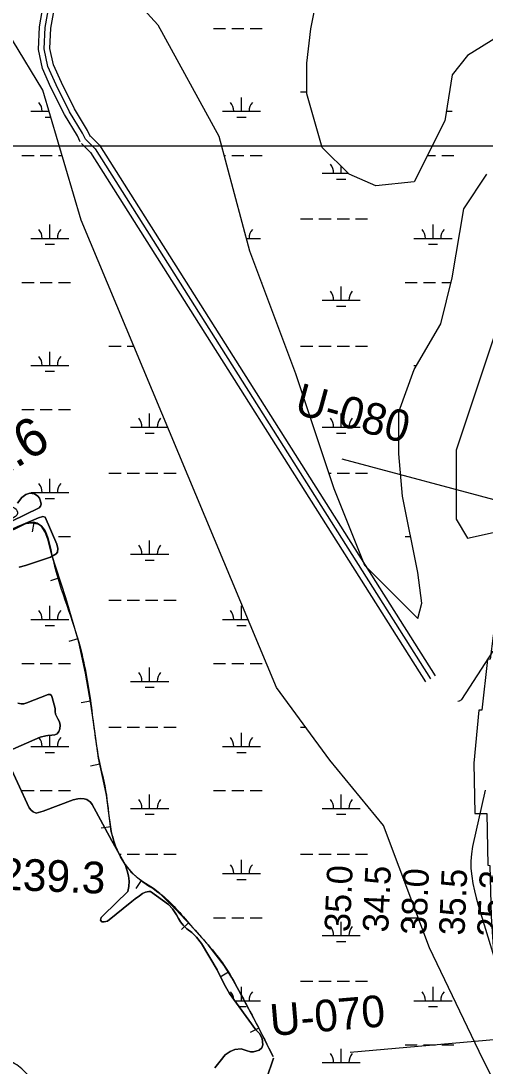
# Model space of a CAD drawing. Extents: x 3281947 to 3319794, y 715894 to 741249.
# Drawn here: x 3293405 to 3294621, y 730987 to 733724 of the extents above; entities that cross this region are included whole.
import ezdxf

# ---------------------------------------------------------------- set-up
doc = ezdxf.new("R2010")
doc.units = 0
for name, color, linetype in [('V-BORW-LINE', 7, 'Continuous'), ('V-GRID-MAJR', 7, 'Continuous'), ('V-RIVR-RANG', 7, 'Continuous'), ('V-RIVR-RANG-IDEN', 7, 'Continuous'), ('V-ROAD-CNTR', 7, 'Continuous'), ('V-RRAP-RVMT', 7, 'Continuous'), ('V-SITE-VEGE', 7, 'Continuous'), ('V-SURV-IDEN', 7, 'Continuous'), ('V-TOPO-MINR', 7, 'Continuous'), ('V-WETL-SWMP', 7, 'Continuous')]:
    doc.layers.add(name, color=color, linetype=linetype)

msp = doc.modelspace()

# ---------------------------------------------------------------- linework, layer by layer
at = {"layer": 'V-BORW-LINE'}
for p, q in [((3293438.9, 732410.6), (3293434.1, 732386.1)), ((3293505.8, 732265.2), (3293482, 732257.5)), ((3293554, 732105.8), (3293530, 732098.8)), ((3293586.8, 731942.5), (3293562.2, 731938.2)), ((3293611.6, 731777.8), (3293587.1, 731772.8)), ((3293640, 731613.7), (3293615.2, 731610.4)), ((3293720.1, 731472.8), (3293705.8, 731452.3)), ((3293843.5, 731362.2), (3293825.3, 731345.1)), ((3293948.3, 731233), (3293927, 731219.7)), ((3294027.8, 731086.6), (3294005.5, 731075.3))]:
    msp.add_line(p, q, dxfattribs=at)
for points in [[(3294065.4, 731012.3), (3294021.6, 731098.9), (3293976, 731184.6), (3293957.6, 731218), (3293937.4, 731250.3), (3293895.2, 731304.6), (3293849.4, 731356), (3293809.7, 731398.2), (3293768.8, 731439), (3293752, 731452.5), (3293724.5, 731469.8), (3293711, 731479.2), (3293698.6, 731490.3), (3293678.2, 731515.3), (3293665.5, 731535.4), (3293650.9, 731567.6), (3293641.6, 731601.6), (3293635.2, 731649.3), (3293628.6, 731696.8), (3293618.2, 731745.2), (3293608.4, 731793.7), (3293598.1, 731864.4), (3293588.1, 731935.2), (3293573.9, 732016.3), (3293556.5, 732096.9), (3293522.7, 732213.3), (3293485.1, 732328.5), (3293475.3, 732366.4), (3293468.6, 732384.7), (3293457.9, 732401.3), (3293447.7, 732408.8), (3293437.4, 732410.9), (3293417.2, 732406.7), (3293352.9, 732375.1)], [(3294066.6, 731007.9), (3294048.3, 730953.6), (3294015.3, 730962.9), (3293968.2, 730832.8), (3293984.4, 730712.4), (3294025, 730625.2), (3294125.7, 730665.2), (3294411.3, 730593.9), (3294443.6, 730454.8), (3294455, 730377), (3294542.3, 730379.8), (3294572, 730312), (3294499.3, 730155.1), (3294304.7, 730084.1), (3294182.8, 729985.9), (3294081.7, 729899.7), (3294039.9, 729833.7), (3293988.3, 729835.4), (3293949.1, 729896), (3293892.4, 730001.9), (3293812.2, 730136.7), (3293762.4, 730233), (3293692.2, 730362.3), (3293538.9, 730574.2)], [(3293538.9, 730574.2), (3293692.2, 730362.3), (3293762.4, 730233), (3293812.2, 730136.7), (3293892.4, 730001.9), (3293949.1, 729896), (3293988.3, 729835.4), (3294039.9, 729833.7), (3294084.7, 729890.8), (3294221.5, 730018.7), (3294337.4, 730090), (3294499.3, 730155.1), (3294572, 730312), (3294542.3, 730379.8), (3294455, 730377), (3294443.6, 730454.8), (3294411.3, 730593.9), (3294125.7, 730665.2), (3294025, 730625.2), (3293984.4, 730712.4), (3293968.2, 730832.8), (3294015.3, 730962.9), (3294048.3, 730953.6), (3294066.6, 731007.9)]]:
    msp.add_lwpolyline(points, dxfattribs=at)
msp.add_spline([(3293535.9, 730584.4), (3293535.4, 730585.3), (3293497, 730657.8), (3293473.2, 730709), (3293458.5, 730751), (3293474.3, 730774.9), (3293498.1, 730803.8), (3293503.4, 730822.7), (3293477.8, 730865.6), (3293442, 730902.7), (3293433.9, 730945), (3293411.4, 730975.9), (3293373.6, 730999.6), (3293329.4, 731009.5), (3293303.1, 731048.1), (3293262.2, 731107.9), (3293205.3, 731214.8), (3293152.6, 731305), (3293107.1, 731394.1), (3293067.5, 731500.7), (3293026.1, 731639), (3292993.6, 731735.4), (3292952.7, 731872.8), (3292925.4, 731981.1), (3292877.6, 732144.9), (3292823.1, 732324.3), (3292751.1, 732547.8), (3292686.3, 732753.5), (3292626.9, 732959.9), (3292578, 733149.6), (3292517.3, 733327.2), (3292468.2, 733513.4), (3292419.2, 733671.8), (3292416, 733774.3), (3292443.1, 733955.9), (3292470.5, 734116.1), (3292505.3, 734342.4), (3292539, 734502.7), (3292585.4, 734750.4), (3292605.6, 734909.3), (3292653.5, 735109.1), (3292667, 735197.9), (3292695.9, 735272.4), (3292816.4, 735423.9), (3292992.8, 735589.4), (3293118.5, 735717.8), (3293151.4, 735720.6), (3293212.8, 735688.5), (3293267.6, 735628.9), (3293299.6, 735578.7), (3293301.8, 735551.8), (3293258, 735404.8), (3293178.9, 735247.8), (3293118.6, 735154.6), (3293020.3, 735075.8), (3292963, 735023.3), (3292899.5, 734947.4), (3292877.5, 734825.5), (3292893.6, 734715.3), (3292909.1, 734596.9), (3292894.2, 734486.7), (3292877, 734359.2), (3292869.2, 734210.8), (3292882, 734024.1), (3292899.4, 733885.4), (3292922.7, 733752.5), (3292923.7, 733661.1), (3292932, 733561), (3292981.6, 733412.2), (3293062.5, 733212.5), (3293111.5, 733047.6), (3293198.7, 732785.6), (3293276, 732606.5), (3293315.6, 732497), (3293336.7, 732448.1), (3293389.1, 732447.8), (3293396.1, 732434.3), (3293380.9, 732420.2), (3293299, 732384.1), (3293266.7, 732364.9), (3293242, 732348.4), (3293249.1, 732332.4), (3293352.9, 732375.1), (3293457.9, 732401.3), (3293485.1, 732328.5), (3293556.5, 732096.9), (3293588.1, 731935.2), (3293608.4, 731793.7), (3293628.6, 731696.8), (3293641.6, 731601.6), (3293698.6, 731490.3), (3293768.8, 731439), (3293849.4, 731356), (3293937.4, 731250.3), (3293976, 731184.6), (3294065.4, 731012.3)], degree=3, dxfattribs=at)
at = {"layer": 'V-GRID-MAJR'}
msp.add_spline([(3286081.5, 733394.4), (3291329.7, 733395.6), (3296577.9, 733397.5), (3301826.1, 733400.1), (3307074.3, 733403.6), (3312322.5, 733407.8), (3317570.7, 733412.7)], degree=3, dxfattribs=at)
at = {"layer": 'V-RIVR-RANG'}
for p, q in [((3294245.3, 732577.4), (3295520.5, 732236.1)), ((3294266.9, 731023.3), (3295442.3, 731126.6))]:
    msp.add_line(p, q, dxfattribs=at)
at = {"layer": 'V-ROAD-CNTR'}
for points in [[(3293560.3, 733407.4), (3293552.9, 733422.8), (3293518.9, 733478.9), (3293483.5, 733549.6), (3293461.3, 733599.4), (3293450.6, 733649.1), (3293453.2, 733708.2), (3293463.8, 733768.2)], [(3293573.8, 733414), (3293566.1, 733429.9), (3293532.1, 733486.1), (3293497.1, 733556), (3293475.6, 733604.1), (3293465.6, 733650.4), (3293468.1, 733706.6), (3293478.5, 733765.3)], [(3293587.3, 733420.5), (3293579.3, 733437.1), (3293545.2, 733493.4), (3293510.7, 733562.5), (3293490, 733608.8), (3293480.7, 733651.7), (3293483, 733704.9), (3293493.3, 733762.5)], [(3293573.8, 733414), (3293599.3, 733389), (3294477.3, 732001.2)], [(3293584.3, 733424.7), (3293611, 733398.5), (3294489.9, 732009.2)], [(3293563.3, 733403.2), (3293587.5, 733379.5), (3294464.6, 731993.1)]]:
    msp.add_lwpolyline(points, dxfattribs=at)
at = {"layer": 'V-RRAP-RVMT'}
msp.add_lwpolyline([(3294917, 732419.7), (3294695.4, 732452.1), (3294671.8, 732315.8), (3294667.4, 732316.1), (3294647.2, 732175.3), (3294649.4, 732174.7), (3294634, 732052.3), (3294626.5, 732052.1), (3294612.3, 731919.3), (3294603.8, 731919.4), (3294591, 731780.6), (3294593.8, 731648.3), (3294624.8, 731648.7), (3294627.6, 731512.8), (3294632.8, 731512.7), (3294636.8, 731379.2), (3294644.9, 731245.9), (3294672.3, 731248.1)], dxfattribs=at)
at = {"layer": 'V-SITE-VEGE'}
for points in [[(3293396.1, 732460.9), (3293406.8, 732475.7), (3293418, 732483.9), (3293428.5, 732487.3), (3293440, 732485.2), (3293449.1, 732479.6), (3293453.1, 732473.8), (3293455.9, 732465.9), (3293457.6, 732458.4), (3293456, 732453), (3293453, 732448.6), (3293379.3, 732412.9)], [(3293308.2, 732362.6), (3293450.5, 732422.4), (3293462, 732425.7), (3293468.3, 732424.5), (3293468.5, 732424.8), (3293499.2, 732353.6), (3293501.2, 732342.2), (3293500.3, 732332.8), (3293496.8, 732328.1), (3293482.1, 732319.6), (3293417, 732297.4), (3293400.2, 732293.5)], [(3293397.1, 731937.7), (3293405.1, 731935.6), (3293412.8, 731935.7), (3293420.3, 731938), (3293476.5, 731959.8), (3293481.4, 731960.1), (3293484.5, 731957.7), (3293486.4, 731952.4), (3293494.7, 731923), (3293494.7, 731915.2), (3293495.2, 731908.2), (3293497.6, 731902.9), (3293501.6, 731896.6), (3293506.1, 731888.4), (3293507.7, 731879.5), (3293506.6, 731869.9), (3293504.3, 731862.9), (3293499.4, 731857.5), (3293493.8, 731854.7), (3293485.9, 731853.5), (3293475.6, 731852.3), (3293469.8, 731852), (3293455.3, 731848.2), (3293369.9, 731810.9)], [(3293365.3, 731796.1), (3293426.7, 731663.6), (3293431.6, 731656.8), (3293436.8, 731652.7), (3293445.2, 731649.2), (3293463.4, 731654.7), (3293541.6, 731684.2), (3293553.5, 731687.1), (3293561.5, 731687.8), (3293570.8, 731687.2)], [(3293570.8, 731687.2), (3293577.8, 731684.9), (3293586.8, 731678.4), (3293591.5, 731672.1), (3293601.8, 731653.2), (3293642.9, 731577.2), (3293678.2, 731515.1), (3293683.4, 731498.1), (3293686.3, 731485.3), (3293688.2, 731471.2), (3293687.8, 731457.4), (3293684.9, 731444.1), (3293621.3, 731382.6), (3293615.3, 731376.4), (3293613, 731369), (3293617, 731364.8), (3293623.3, 731364.6), (3293631.7, 731366.9), (3293695.5, 731417.7), (3293704.1, 731424.6), (3293715.1, 731433), (3293723.7, 731439.1), (3293731.4, 731442.9), (3293740, 731444.6), (3293744, 731444.1), (3293791.2, 731410), (3293801.5, 731398.8), (3293812.3, 731383.4), (3293817.5, 731373.4), (3293822.5, 731365), (3293830, 731355.9), (3293839.8, 731346.6), (3293852.5, 731336.6), (3293865, 731325), (3293877.7, 731308.2), (3293918.4, 731238.7), (3293936.8, 731201.9), (3293951.4, 731177.2), (3294020.4, 731082.3), (3294029.8, 731072.3), (3294037.1, 731059.3), (3294038.3, 731043.1), (3294036, 731034.5), (3294028.8, 731028.4), (3294014.1, 731024.6), (3294006.4, 731024.3), (3293994.7, 731027.7), (3293982, 731032.4), (3293965.2, 731030.9), (3293953.3, 731025.7), (3293939.8, 731016.3), (3293926.3, 731000.3), (3293912.4, 730982.7)]]:
    msp.add_lwpolyline(points, dxfattribs=at)
at = {"layer": 'V-TOPO-MINR'}
for points in [[(3294549.5, 731942.9), (3294553.9, 731943.4), (3294559.9, 731946.6), (3294641.3, 732073.6)], [(3294620.8, 731709.7), (3294588, 731561.8), (3294584.9, 731542.7), (3294583.2, 731523.4), (3294583.6, 731504.1), (3294585.5, 731484.8), (3294588.8, 731465.5), (3294592.8, 731446.4), (3294597.5, 731427.4), (3294602.8, 731408.5), (3294738.5, 730962.5)]]:
    msp.add_lwpolyline(points, dxfattribs=at)
at = {"layer": 'V-WETL-SWMP'}
for p, q in [((3293909, 733704.3), (3293941, 733704.3)), ((3293957, 733704.3), (3293989, 733704.3)), ((3294005, 733704.3), (3294037, 733704.3)), ((3293982.4, 733487.1), (3293982.4, 733523.1)), ((3294137, 733537.8), (3294153.9, 733537.8)), ((3293430.5, 733487.1), (3293478.9, 733487.1)), ((3293468.5, 733471.6), (3293483.4, 733471.6)), ((3293932.4, 733487.1), (3294032.4, 733487.1)), ((3293970.4, 733471.6), (3293994.4, 733471.6)), ((3294518.8, 733487.1), (3294534.3, 733487.1)), ((3293407.1, 733371.6), (3293439.1, 733371.6)), ((3293455.1, 733371.6), (3293487.1, 733371.6)), ((3293503.1, 733371.6), (3293512.8, 733371.6)), ((3293937, 733371.6), (3293941, 733371.6)), ((3293957, 733371.6), (3293989, 733371.6)), ((3294005, 733371.6), (3294037, 733371.6)), ((3294469.3, 733371.6), (3294490.9, 733371.6)), ((3294506.9, 733371.6), (3294538.9, 733371.6)), ((3294193.8, 733325.2), (3294261, 733325.2)), ((3294243.8, 733325.2), (3294243.8, 733342.4)), ((3294231.8, 733309.8), (3294255.8, 733309.8)), ((3293480.5, 733154.4), (3293480.5, 733190.4)), ((3294137, 733205.1), (3294169, 733205.1)), ((3294185, 733205.1), (3294217, 733205.1)), ((3294233, 733205.1), (3294265, 733205.1)), ((3294281, 733205.1), (3294313, 733205.1)), ((3294484.3, 733154.4), (3294484.3, 733190.4)), ((3293430.5, 733154.4), (3293530.5, 733154.4)), ((3293468.5, 733139), (3293492.5, 733139)), ((3293994.9, 733154.4), (3294032.4, 733154.4)), ((3294434.3, 733154.4), (3294534.3, 733154.4)), ((3294472.3, 733139), (3294496.3, 733139)), ((3293407.1, 733039), (3293439.1, 733039)), ((3293455.1, 733039), (3293487.1, 733039)), ((3293503.1, 733039), (3293535.1, 733039)), ((3294034.6, 733039), (3294037, 733039)), ((3294243.8, 732992.5), (3294243.8, 733028.5)), ((3294410.9, 733039), (3294442.9, 733039)), ((3294458.9, 733039), (3294490.9, 733039)), ((3294506.9, 733039), (3294531.7, 733039)), ((3294193.8, 732992.5), (3294293.8, 732992.5)), ((3294231.8, 732977.1), (3294255.8, 732977.1)), ((3293635.1, 732872.5), (3293667.1, 732872.5)), ((3293683.1, 732872.5), (3293700.3, 732872.5)), ((3294137, 732872.5), (3294169, 732872.5)), ((3294185, 732872.5), (3294217, 732872.5)), ((3294233, 732872.5), (3294265, 732872.5)), ((3294281, 732872.5), (3294313, 732872.5)), ((3293480.5, 732821.7), (3293480.5, 732857.7)), ((3293430.5, 732821.7), (3293530.5, 732821.7)), ((3293468.5, 732806.3), (3293492.5, 732806.3)), ((3294434.3, 732821.7), (3294441, 732821.7)), ((3293407.1, 732706.3), (3293439.1, 732706.3)), ((3293455.1, 732706.3), (3293487.1, 732706.3)), ((3293503.1, 732706.3), (3293535.1, 732706.3)), ((3293741.9, 732659.9), (3293741.9, 732695.9)), ((3294243.8, 732659.9), (3294243.8, 732695.9)), ((3293691.9, 732659.9), (3293789.1, 732659.9)), ((3293729.9, 732644.4), (3293753.9, 732644.4)), ((3294193.8, 732659.9), (3294293.8, 732659.9)), ((3294231.8, 732644.4), (3294255.8, 732644.4)), ((3293635.1, 732539.8), (3293667.1, 732539.8)), ((3293683.1, 732539.8), (3293715.1, 732539.8)), ((3293731.1, 732539.8), (3293763.1, 732539.8)), ((3293779.1, 732539.8), (3293811.1, 732539.8)), ((3294210.7, 732539.8), (3294217, 732539.8)), ((3294233, 732539.8), (3294265, 732539.8)), ((3294281, 732539.8), (3294313, 732539.8)), ((3293480.5, 732489), (3293480.5, 732525)), ((3293430.5, 732489), (3293530.5, 732489)), ((3293468.5, 732473.6), (3293492.5, 732473.6)), ((3293503.1, 732373.6), (3293535.1, 732373.6)), ((3294410.9, 732373.6), (3294425.7, 732373.6)), ((3293741.9, 732327.2), (3293741.9, 732363.2)), ((3293691.9, 732327.2), (3293791.9, 732327.2)), ((3294293, 732327.2), (3294293.8, 732327.2)), ((3293729.9, 732311.7), (3293753.9, 732311.7)), ((3293635.1, 732207.1), (3293667.1, 732207.1)), ((3293683.1, 732207.1), (3293715.1, 732207.1)), ((3293731.1, 732207.1), (3293763.1, 732207.1)), ((3293779.1, 732207.1), (3293811.1, 732207.1)), ((3293480.5, 732156.4), (3293480.5, 732192.4)), ((3293982.4, 732156.4), (3293982.4, 732192.4)), ((3293430.5, 732156.4), (3293530.5, 732156.4)), ((3293932.4, 732156.4), (3293999.4, 732156.4)), ((3293468.5, 732140.9), (3293492.5, 732140.9)), ((3293970.4, 732140.9), (3293994.4, 732140.9)), ((3293407.1, 732040.9), (3293439.1, 732040.9)), ((3293455.1, 732040.9), (3293487.1, 732040.9)), ((3293503.1, 732040.9), (3293535.1, 732040.9)), ((3293909, 732040.9), (3293941, 732040.9)), ((3293957, 732040.9), (3293989, 732040.9)), ((3294005, 732040.9), (3294037, 732040.9)), ((3293741.9, 731994.5), (3293741.9, 732030.5)), ((3293691.9, 731994.5), (3293791.9, 731994.5)), ((3293729.9, 731979.1), (3293753.9, 731979.1)), ((3293635.1, 731874.4), (3293667.1, 731874.4)), ((3293683.1, 731874.4), (3293715.1, 731874.4)), ((3293731.1, 731874.4), (3293763.1, 731874.4)), ((3293779.1, 731874.4), (3293811.1, 731874.4)), ((3294137, 731874.4), (3294150.2, 731874.4)), ((3293480.5, 731823.7), (3293480.5, 731852.8)), ((3293982.4, 731823.7), (3293982.4, 731859.7)), ((3293430.5, 731823.7), (3293530.5, 731823.7)), ((3293932.4, 731823.7), (3294032.4, 731823.7)), ((3293468.5, 731808.3), (3293492.5, 731808.3)), ((3293970.4, 731808.3), (3293994.4, 731808.3)), ((3293407.1, 731708.3), (3293439.1, 731708.3)), ((3293455.1, 731708.3), (3293487.1, 731708.3)), ((3293503.1, 731708.3), (3293535.1, 731708.3)), ((3293741.9, 731661.8), (3293741.9, 731697.8)), ((3293909, 731708.3), (3293941, 731708.3)), ((3293957, 731708.3), (3293989, 731708.3)), ((3294005, 731708.3), (3294037, 731708.3)), ((3294243.8, 731661.8), (3294243.8, 731697.8)), ((3293691.9, 731661.8), (3293791.9, 731661.8)), ((3294193.8, 731661.8), (3294293.8, 731661.8)), ((3293729.9, 731646.4), (3293753.9, 731646.4)), ((3294231.8, 731646.4), (3294255.8, 731646.4)), ((3293663.1, 731541.8), (3293667.1, 731541.8)), ((3293683.1, 731541.8), (3293715.1, 731541.8)), ((3293731.1, 731541.8), (3293763.1, 731541.8)), ((3293779.1, 731541.8), (3293811.1, 731541.8)), ((3293982.4, 731491), (3293982.4, 731527)), ((3294137, 731541.8), (3294169, 731541.8)), ((3294185, 731541.8), (3294217, 731541.8)), ((3294233, 731541.8), (3294265, 731541.8)), ((3294281, 731541.8), (3294313, 731541.8)), ((3293932.4, 731491), (3294032.4, 731491)), ((3293970.4, 731475.6), (3293994.4, 731475.6)), ((3293909, 731375.6), (3293941, 731375.6)), ((3293957, 731375.6), (3293989, 731375.6)), ((3294005, 731375.6), (3294037, 731375.6)), ((3294243.8, 731329.2), (3294243.8, 731365.2)), ((3294410.9, 731375.6), (3294442.9, 731375.6)), ((3294193.8, 731329.2), (3294293.8, 731329.2)), ((3294231.8, 731313.7), (3294255.8, 731313.7)), ((3293982.4, 731158.3), (3293982.4, 731194.3)), ((3294137, 731209.1), (3294169, 731209.1)), ((3294185, 731209.1), (3294217, 731209.1)), ((3294233, 731209.1), (3294265, 731209.1)), ((3294281, 731209.1), (3294313, 731209.1)), ((3294484.3, 731158.3), (3294484.3, 731194.3)), ((3293965.1, 731158.3), (3294032.4, 731158.3)), ((3293976.4, 731142.9), (3293994.4, 731142.9)), ((3294434.3, 731158.3), (3294534.3, 731158.3)), ((3294472.3, 731142.9), (3294496.3, 731142.9)), ((3294243.8, 730996.5), (3294243.8, 731032.5)), ((3294410.9, 731042.9), (3294442.9, 731042.9)), ((3294458.9, 731042.9), (3294490.9, 731042.9)), ((3294506.9, 731042.9), (3294538.9, 731042.9)), ((3294193.8, 730996.5), (3294293.8, 730996.5))]:
    msp.add_line(p, q, dxfattribs=at)
for points in [[(3294819.9, 730595.5), (3294614.9, 731005.5), (3294474.6, 731296.3), (3294354.4, 731617.2), (3294214.1, 731787.7), (3294073.8, 731978.2), (3293562.7, 733201.7), (3293462.5, 733542.7), (3293382.4, 733673.1), (3293352.3, 733793.4), (3293412.4, 733883.7), (3293492.6, 733913.7), (3293612.8, 733883.7), (3293673, 733813.5), (3293763.1, 733713.2)], [(3294655, 733683.1), (3294574.8, 733632.9), (3294534.7, 733582.8), (3294514.7, 733462.5), (3294434.5, 733302), (3294334.3, 733292), (3294264.2, 733322.1), (3294194, 733392.3), (3294154, 733532.7), (3294154, 733612.9), (3294164, 733703.1), (3294184, 733803.4)], [(3293763.1, 733713.2), (3293923.5, 733422.3), (3294003.6, 733121.5), (3294123.9, 732800.6), (3294224.1, 732499.7), (3294304.3, 732299.1), (3294444.6, 732158.7), (3294454.6, 732198.9), (3294444.6, 732279.1), (3294404.5, 732479.7), (3294394.4, 732590), (3294394.4, 732700.3), (3294434.5, 732810.6), (3294504.7, 732930.9), (3294534.7, 733051.3), (3294564.8, 733231.8), (3294624.9, 733322.1)], [(3294645, 732900.9), (3294544.8, 732600), (3294544.8, 732419.5), (3294574.8, 732369.3), (3294665, 732389.4)], [(3293379.3, 732412.9), (3293453, 732448.6), (3293456, 732453), (3293457.6, 732458.4), (3293455.9, 732465.9), (3293453.1, 732473.8), (3293449.1, 732479.6), (3293440, 732485.2), (3293428.5, 732487.3), (3293418, 732483.9), (3293406.8, 732475.7), (3293396.1, 732460.9)], [(3293400.2, 732293.5), (3293417, 732297.4), (3293482.1, 732319.6), (3293496.8, 732328.1), (3293500.3, 732332.8), (3293501.2, 732342.2), (3293499.2, 732353.6), (3293468.5, 732424.8), (3293468.3, 732424.5), (3293462, 732425.7), (3293450.5, 732422.4), (3293308.2, 732362.6)], [(3293369.9, 731810.9), (3293455.3, 731848.2), (3293469.8, 731852), (3293475.6, 731852.3), (3293485.9, 731853.5), (3293493.8, 731854.7), (3293499.4, 731857.5), (3293504.3, 731862.9), (3293506.6, 731869.9), (3293507.7, 731879.5), (3293506.1, 731888.4), (3293501.6, 731896.6), (3293497.6, 731902.9), (3293495.2, 731908.2), (3293494.7, 731915.2), (3293494.7, 731923), (3293486.4, 731952.4), (3293484.5, 731957.7), (3293481.4, 731960.1), (3293476.5, 731959.8), (3293420.3, 731938), (3293412.8, 731935.7), (3293405.1, 731935.6)], [(3293405.1, 731935.6), (3293397.1, 731937.7)], [(3293912.4, 730982.7), (3293926.3, 731000.3), (3293939.8, 731016.3), (3293953.3, 731025.7), (3293965.2, 731030.9), (3293982, 731032.4), (3293994.7, 731027.7), (3294006.4, 731024.3), (3294014.1, 731024.6), (3294028.8, 731028.4), (3294036, 731034.5), (3294038.3, 731043.1), (3294037.1, 731059.3), (3294029.8, 731072.3), (3294020.4, 731082.3), (3293951.4, 731177.2), (3293936.8, 731201.9), (3293918.4, 731238.7), (3293877.7, 731308.2), (3293865, 731325), (3293852.5, 731336.6), (3293839.8, 731346.6), (3293830, 731355.9), (3293822.5, 731365), (3293817.5, 731373.4), (3293812.3, 731383.4), (3293801.5, 731398.8), (3293791.2, 731410), (3293744, 731444.1), (3293740, 731444.6), (3293731.4, 731442.9), (3293723.7, 731439.1), (3293715.1, 731433), (3293704.1, 731424.6), (3293695.5, 731417.7), (3293631.7, 731366.9), (3293623.3, 731364.6), (3293617, 731364.8), (3293613, 731369), (3293615.3, 731376.4), (3293621.3, 731382.6), (3293684.9, 731444.1), (3293687.8, 731457.4), (3293688.2, 731471.2), (3293686.3, 731485.3), (3293683.4, 731498.1), (3293678.2, 731515.1), (3293642.9, 731577.2), (3293601.8, 731653.2), (3293591.5, 731672.1), (3293586.8, 731678.4), (3293577.8, 731684.9), (3293570.8, 731687.2), (3293561.5, 731687.8), (3293553.5, 731687.1), (3293541.6, 731684.2), (3293463.4, 731654.7), (3293445.2, 731649.2), (3293436.8, 731652.7), (3293431.6, 731656.8), (3293426.7, 731663.6), (3293365.3, 731796.1)]]:
    msp.add_lwpolyline(points, dxfattribs=at)
for centre, start, end in [((3293425.3, 733487.5), 359.2282, 40.7718), ((3293927.2, 733487.5), 359.2282, 40.7718), ((3294037.6, 733487.5), 139.2282, 180.7718), ((3294188.6, 733325.7), 359.2282, 40.7718), ((3293425.3, 733154.9), 359.2282, 40.7718), ((3293535.7, 733154.9), 139.2282, 180.7718), ((3294037.6, 733154.9), 139.2282, 180.7718), ((3294429.1, 733154.9), 359.2282, 40.7718), ((3294539.6, 733154.9), 139.2282, 180.7718), ((3294188.6, 732993), 359.2282, 40.7718), ((3294299.1, 732993), 139.2282, 180.7718), ((3293425.3, 732822.2), 359.2282, 40.7718), ((3293535.7, 732822.2), 139.2282, 180.7718), ((3293686.7, 732660.3), 359.2282, 40.7718), ((3293797.2, 732660.3), 139.2282, 180.7718), ((3294188.6, 732660.3), 359.2282, 40.7718), ((3294299.1, 732660.3), 139.2282, 180.7718), ((3293425.3, 732489.5), 359.2282, 40.7718), ((3293535.7, 732489.5), 139.2282, 180.7718), ((3293686.7, 732327.7), 359.2282, 40.7718), ((3293797.2, 732327.7), 139.2282, 180.7718), ((3293425.3, 732156.8), 359.2282, 40.7718), ((3293535.7, 732156.8), 139.2282, 180.7718), ((3293927.2, 732156.8), 359.2282, 40.7718), ((3293686.7, 731995), 359.2282, 40.7718), ((3293797.2, 731995), 139.2282, 180.7718), ((3293425.3, 731824.2), 359.2282, 40.0828), ((3293535.7, 731824.2), 139.2282, 180.7718), ((3293927.2, 731824.2), 359.2282, 40.7718), ((3294037.7, 731824.2), 139.2282, 180.7718), ((3293686.7, 731662.3), 359.2282, 40.7718), ((3293797.2, 731662.3), 139.2282, 180.7718), ((3294188.6, 731662.3), 359.2282, 40.7718), ((3294299.1, 731662.3), 139.2282, 180.7718), ((3293927.2, 731491.5), 359.2282, 40.7718), ((3294037.7, 731491.5), 139.2282, 180.7718), ((3294188.6, 731329.6), 359.2282, 40.7718), ((3294299.1, 731329.6), 139.2282, 180.7718), ((3293927.2, 731158.8), 5.7312, 40.7718), ((3294037.7, 731158.8), 139.2282, 180.7718), ((3294429.1, 731158.8), 359.2282, 40.7718), ((3294539.6, 731158.8), 139.2282, 180.7718), ((3294188.6, 730997), 359.2282, 40.7718), ((3294299.1, 730997), 139.2282, 180.7718)]:
    msp.add_arc(centre, 35.2, start, end, dxfattribs=at)

# ---------------------------------------------------------------- texts
at = {"layer": 'V-RIVR-RANG'}
for s, p in [('35.0', (3294266.6, 731337.3)), ('34.5', (3294366.6, 731336.2)), ('38.0', (3294466.4, 731329.3)), ('35.5', (3294566.5, 731328.2)), ('25.3', (3294666.4, 731324.1))]:
    msp.add_text(s, height=67, rotation=87.5483, dxfattribs=at).set_placement(p)
at = {"layer": 'V-RIVR-RANG-IDEN'}
for s, rotation, p in [('U-080', 344.8723, (3294118, 732696.3)), ('R-239.3', 357.6936, (3293230, 731454.1)), ('U-070', 4.8803, (3294060.3, 731065.7))]:
    msp.add_text(s, height=83, rotation=rotation, dxfattribs=at).set_placement(p)
at = {"layer": 'V-SURV-IDEN'}
msp.add_text('3227+72.6', height=100, rotation=31.076, dxfattribs=at).set_placement((3292942.7, 732280.7))

doc.saveas('drawing.dxf')
